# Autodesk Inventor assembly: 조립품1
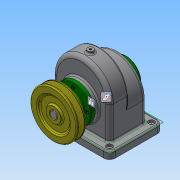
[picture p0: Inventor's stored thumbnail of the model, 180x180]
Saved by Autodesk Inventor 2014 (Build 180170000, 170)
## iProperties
Created: 2017-11
Part Number: 조립품1
Document SubType Name: Assembly
Designer: NET
Author: NET
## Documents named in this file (14)
- C:\Users\NET\Desktop\471107v1039\조립품1.iam
- C:\Users\NET\Desktop\471107v1039\본체.ipt
- C:\Users\NET\Desktop\471107v1039\뒤커버.ipt
- C:\Users\NET\Desktop\471107v1039\베어링 6002.ipt
- C:\Users\NET\Desktop\471107v1039\축.ipt
- C:\Users\NET\Desktop\471107v1039\앞커버.ipt
- C:\Users\NET\Desktop\471107v1039\스퍼기어.ipt
- C:\Users\NET\Desktop\471107v1039\오일 실 15 30 7.ipt
- C:\Users\NET\Desktop\471107v1039\키 - 6 x 6 x 22.ipt
- C:\Users\NET\Desktop\471107v1039\키 - 5 x 5 x 18.ipt
- C:\Users\NET\Desktop\471107v1039\V-벨트풀리.ipt
- C:\Users\NET\Desktop\471107v1039\볼트 M3 x 8.ipt
- C:\Users\NET\Desktop\471107v1039\멈춤나사 - M4 x 10.ipt
- 멈춤나사 - M4 x 10.ipt
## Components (1 placed, 1 different names)
1. V-벨트풀리:1
